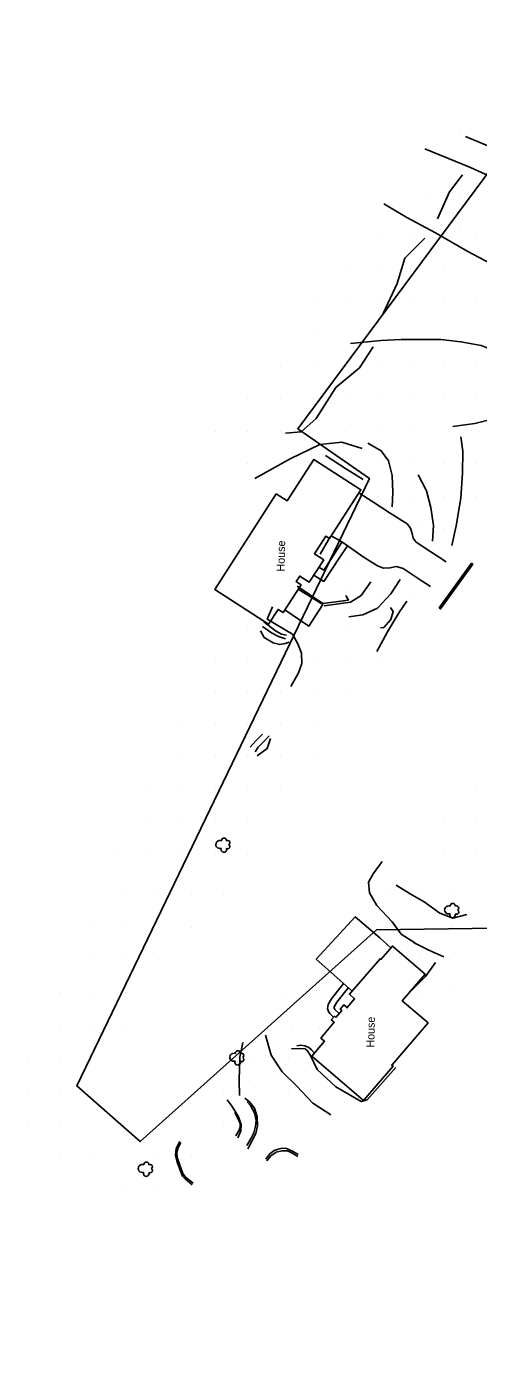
# Model space of a CAD drawing. Extents: x 19528164 to 19545171, y 7585743 to 7602745.
# Drawn here: x 19530134 to 19530412, y 7589849 to 7590664 of the extents above; entities that cross this region are included whole.
import ezdxf

# ---------------------------------------------------------------- set-up
doc = ezdxf.new("R2010")
doc.units = 0
for name, color, linetype in [('PhoBreakLine', 7, 'Continuous'), ('PhoBuilding', 7, 'Continuous'), ('PhoConcreteSlab', 7, 'Continuous'), ('PhoCulvert', 7, 'Continuous'), ('PhoEdgeEntrancePaved', 7, 'Continuous'), ('PhoEdgeSidewalk', 7, 'Continuous'), ('PhoISAEPoints', 7, 'Continuous'), ('PhoNotesDesign', 7, 'Continuous'), ('PhoRetainingWall', 7, 'Continuous'), ('PhoSurveyLimits', 7, 'Continuous'), ('PhoVegetation', 7, 'Continuous')]:
    doc.layers.add(name, color=color, linetype=linetype)

msp = doc.modelspace()

# ---------------------------------------------------------------- linework, layer by layer
at = {"layer": 'PhoBreakLine'}
msp.add_line((19530314.36, 7590339.33), (19530320.5, 7590350.04), dxfattribs=at)
for points in [[(19530403.61, 7590596.1), (19530418.38, 7590589.9), (19530432.36, 7590583.52), (19530438.39, 7590577.61), (19530460.96, 7590568.14), (19530473.26, 7590563.33)], [(19530378.62, 7590588.6), (19530406.66, 7590577.14), (19530432.03, 7590565.59), (19530461.15, 7590553.18), (19530486.35, 7590541.22), (19530503.6, 7590532.1)], [(19530386.5, 7590545.53), (19530393.89, 7590562.23), (19530401.77, 7590572.56)], [(19530479.66, 7590482.75), (19530468.31, 7590489.71), (19530454.31, 7590498.48), (19530439.34, 7590506.63), (19530422.54, 7590516.14), (19530405.06, 7590525.46), (19530385.22, 7590536.94), (19530367.64, 7590546.45), (19530353.47, 7590554.82)], [(19530353.07, 7590487.36), (19530361.78, 7590505.73), (19530366.36, 7590521.43), (19530378.64, 7590533.64)], [(19530502.39, 7590491.11), (19530496.31, 7590483.44), (19530489.96, 7590476.5), (19530483.54, 7590468.94), (19530483.54, 7590468.94), (19530476.74, 7590460.48), (19530471.42, 7590454.04), (19530465.97, 7590448.64), (19530460.11, 7590444.11), (19530453.81, 7590439.85), (19530453.66, 7590439.69), (19530447.39, 7590435.22), (19530438.51, 7590429.95), (19530430.65, 7590425.82), (19530420.97, 7590422.56), (19530409.38, 7590419.78), (19530395.92, 7590417.93)], [(19530471.42, 7590454.04), (19530466.34, 7590452.45), (19530457.67, 7590454), (19530445.09, 7590456.61), (19530432.58, 7590460.5), (19530423.57, 7590463.49), (19530413.26, 7590467.63), (19530400.84, 7590469.96), (19530388.45, 7590471.4), (19530374.92, 7590471.35), (19530364.22, 7590471.36), (19530351.67, 7590470.74), (19530333.08, 7590468.91)], [(19530293.09, 7590413.81), (19530302.65, 7590414.63), (19530311.85, 7590422.89), (19530323.97, 7590441.86), (19530338.59, 7590453.99), (19530347.02, 7590466.81)], [(19530274.18, 7590386.01), (19530295.87, 7590398.02), (19530314.16, 7590406.82), (19530327.61, 7590408.34), (19530340.09, 7590404.41)], [(19530358.56, 7590368.47), (19530359.03, 7590377.48), (19530358.71, 7590387.72), (19530356.37, 7590396.83), (19530351.82, 7590403.02), (19530343.65, 7590407.58)], [(19530395.3, 7590344.82), (19530397.89, 7590356.86), (19530400.88, 7590373.93), (19530401.92, 7590389.17), (19530402.11, 7590402.82), (19530400.88, 7590411.54)], [(19530317.73, 7590400.04), (19530330.62, 7590391.73), (19530340.85, 7590385.22)], [(19530383.33, 7590347.47), (19530384.09, 7590357.15), (19530382.43, 7590368.2), (19530379.68, 7590378.43), (19530379.12, 7590379.6), (19530374.58, 7590388.09)], [(19530331.88, 7590300.96), (19530340.62, 7590302.04), (19530349.52, 7590306.34), (19530357.83, 7590314.95), (19530363.61, 7590323.81)], [(19530300.21, 7590319.8), (19530315.99, 7590309.1), (19530331.71, 7590311.17), (19530330.12, 7590314.08)], [(19530316.92, 7590307.62), (19530327.06, 7590309.02), (19530332.96, 7590309.97), (19530339.57, 7590314.04), (19530345.55, 7590322.41)], [(19530285.16, 7590307), (19530281.82, 7590299.45), (19530297.3, 7590290.33), (19530300.55, 7590284.35), (19530302.95, 7590278.54), (19530303.15, 7590272.26), (19530301.14, 7590266.4), (19530296.35, 7590258.05)], [(19530349.17, 7590279.63), (19530355.8, 7590291.67), (19530363.09, 7590304.04), (19530367.7, 7590310.44)], [(19530357.58, 7590306.66), (19530359.3, 7590304.17), (19530357.7, 7590299.34), (19530353.47, 7590294.38), (19530351.4, 7590294.13)], [(19530277.78, 7590292.26), (19530280.04, 7590288.18), (19530285.51, 7590284.84), (19530289.49, 7590283.81), (19530292.87, 7590284.59), (19530295.37, 7590285.41)], [(19530278.89, 7590295.07), (19530284.43, 7590291.04), (19530288.67, 7590288.74), (19530293.16, 7590287.35)], [(19530271.42, 7590220.76), (19530274.67, 7590224.57), (19530278.99, 7590228.8)], [(19530274.4, 7590218.03), (19530276.29, 7590220.77), (19530280.29, 7590224.91), (19530283.05, 7590227.86)], [(19530275.68, 7590215.43), (19530281.77, 7590219.96), (19530283.92, 7590226.04)], [(19530372.47, 7590100.46), (19530364.22, 7590105.87), (19530358.63, 7590113.42), (19530349.29, 7590123.58), (19530344.63, 7590131.28), (19530344, 7590137.88), (19530346.99, 7590143.04), (19530352.55, 7590150.62)], [(19530361.11, 7590136.08), (19530369.6, 7590130.63), (19530378.35, 7590125.69), (19530387.87, 7590118.73), (19530395.8, 7590115.7), (19530404.42, 7590117.9)], [(19530372.22, 7590100.63), (19530381.19, 7590096.1), (19530390.3, 7590091.93)], [(19530369.6, 7590070.5), (19530379.18, 7590079.78), (19530385.27, 7590088.35)], [(19530264.87, 7590006.7), (19530264.66, 7590016.21), (19530265.08, 7590030.34), (19530266.83, 7590039.35)], [(19530280.77, 7590043.73), (19530284.2, 7590031.42), (19530291.01, 7590021.16), (19530299.97, 7590012.45), (19530309.81, 7590001.97), (19530320.88, 7589994.74)], [(19530296.69, 7590035.42), (19530301.87, 7590035.62), (19530305.13, 7590035.33), (19530306.64, 7590034.17), (19530308.38, 7590031.35), (19530312.61, 7590022.6), (19530324, 7590012.11), (19530339.57, 7590002.92), (19530343.23, 7590004.12), (19530360.78, 7590023.84)], [(19530263.83, 7589980.6), (19530265.52, 7589984.96), (19530265.73, 7589988.66), (19530264.21, 7589993.54), (19530260.33, 7590000.04), (19530257.11, 7590004.05)], [(19530269.89, 7589974.02), (19530274.79, 7589983.34), (19530275.78, 7589988), (19530275.68, 7589993.52), (19530273.91, 7589998.85), (19530271.01, 7590002.9), (19530268.14, 7590004.97)], [(19530228.03, 7589978.47), (19530225.81, 7589974.07), (19530225.36, 7589970), (19530226.5, 7589965.75), (19530228.41, 7589960.91), (19530229.84, 7589957.13), (19530231.42, 7589955.45), (19530235.62, 7589951.87)], [(19530281.64, 7589966.54), (19530284.04, 7589969.59), (19530287.29, 7589971.85), (19530290.89, 7589972.74), (19530294.21, 7589972.74), (19530296.6, 7589971.76), (19530300.63, 7589969.22)]]:
    msp.add_lwpolyline(points, dxfattribs=at)
at = {"layer": 'PhoBuilding'}
for points in [[(19530287.38, 7590376.46), (19530249.53, 7590317.78), (19530282.66, 7590296.41), (19530288.5, 7590305.46), (19530291.53, 7590303.5), (19530302.61, 7590320.68), (19530299.64, 7590322.59), (19530301.83, 7590325.99), (19530307.68, 7590322.22), (19530316.53, 7590335.94), (19530310.82, 7590339.62), (19530317.8, 7590350.43), (19530320.05, 7590348.98), (19530339.42, 7590379.01), (19530310.53, 7590397.65), (19530294.08, 7590372.14)], [(19530340.98, 7590003.56), (19530309.23, 7590030.88), (19530317.07, 7590040), (19530314.71, 7590042.04), (19530323.01, 7590051.69), (19530321.22, 7590053.23), (19530323.11, 7590055.42), (19530323.95, 7590054.69), (19530327.63, 7590058.97), (19530326.64, 7590059.81), (19530328.94, 7590062.48), (19530331.07, 7590060.65), (19530330.97, 7590060.54), (19530330.81, 7590060.68), (19530335.56, 7590066.19), (19530332.38, 7590068.93), (19530351.17, 7590090.76), (19530351.69, 7590090.31), (19530358.78, 7590098.55), (19530378.86, 7590081.27), (19530364.81, 7590064.94), (19530380.7, 7590051.27), (19530358.36, 7590025.31), (19530359.13, 7590024.65)]]:
    msp.add_lwpolyline(points, close=True, dxfattribs=at)
at = {"layer": 'PhoConcreteSlab'}
msp.add_lwpolyline([(19530292.6, 7590305.15), (19530307.44, 7590295.23), (19530316.06, 7590308.39), (19530300.86, 7590317.97)], dxfattribs=at)
at = {"layer": 'PhoCulvert'}
msp.add_line((19530387.52, 7590306.39), (19530407.28, 7590333.91), dxfattribs=at)
msp.add_lwpolyline([(19530387.52, 7590306.39), (19530388.33, 7590305.81), (19530408.1, 7590333.33), (19530407.28, 7590333.91)], dxfattribs=at)
at = {"layer": 'PhoEdgeEntrancePaved'}
for points in [[(19530391.88, 7590334.64), (19530377.61, 7590343.85), (19530373.09, 7590347.04), (19530371.6, 7590349.25), (19530370.98, 7590352.17), (19530369.91, 7590355.51), (19530367.73, 7590358.03), (19530357.35, 7590364.65), (19530346.75, 7590371.63), (19530338.16, 7590377.05)], [(19530321.21, 7590350.78), (19530327.64, 7590346.96), (19530341.44, 7590337.43), (19530349.55, 7590332.22), (19530353.28, 7590330.77), (19530357.22, 7590330.94), (19530361.29, 7590331.79), (19530365.28, 7590330.62), (19530376.47, 7590323.24), (19530382.25, 7590319.48)], [(19530334.1, 7590070.92), (19530311.95, 7590090.4), (19530323.95, 7590103.55), (19530335.78, 7590116.48), (19530351.06, 7590103.65), (19530357.79, 7590097.39)]]:
    msp.add_lwpolyline(points, dxfattribs=at)
at = {"layer": 'PhoEdgeSidewalk'}
for points in [[(19530331.08, 7590344.59), (19530326.53, 7590337.64), (19530316.68, 7590322.7), (19530310.45, 7590326.51)], [(19530327.77, 7590346.87), (19530320.87, 7590336.24), (19530316.57, 7590329.66), (19530313.6, 7590331.39)], [(19530328.78, 7590075.6), (19530321.34, 7590066.21), (19530319.24, 7590062.54), (19530318.96, 7590060.26), (19530319.58, 7590058.43), (19530320.3, 7590057.19), (19530322.65, 7590054.89)], [(19530331.75, 7590072.99), (19530324.62, 7590064), (19530323.07, 7590061.27), (19530322.99, 7590060.68), (19530323.2, 7590060.07), (19530323.45, 7590059.64), (19530326.03, 7590057.12)]]:
    msp.add_lwpolyline(points, dxfattribs=at)
at = {"layer": 'PhoISAEPoints'}
for p, q in [((19530400, 7590600), (19530400, 7590600)), ((19530380, 7590560), (19530380, 7590560)), ((19530400, 7590560), (19530400, 7590560)), ((19530350, 7590535), (19530350, 7590535)), ((19530370, 7590535), (19530370, 7590535)), ((19530400, 7590540), (19530400, 7590540)), ((19530410, 7590535), (19530410, 7590535)), ((19530330, 7590515), (19530330, 7590515)), ((19530350, 7590515), (19530350, 7590515)), ((19530370, 7590515), (19530370, 7590515)), ((19530390, 7590515), (19530390, 7590515)), ((19530310, 7590495), (19530310, 7590495)), ((19530330, 7590495), (19530330, 7590495)), ((19530350, 7590495), (19530350, 7590495)), ((19530370, 7590495), (19530370, 7590495)), ((19530390, 7590495), (19530390, 7590495)), ((19530410, 7590495), (19530410, 7590495)), ((19530310, 7590475), (19530310, 7590475)), ((19530290, 7590455), (19530290, 7590455)), ((19530310, 7590455), (19530310, 7590455)), ((19530330, 7590455), (19530330, 7590455)), ((19530350, 7590455), (19530350, 7590455)), ((19530370, 7590455), (19530370, 7590455)), ((19530390, 7590455), (19530390, 7590455)), ((19530410, 7590455), (19530410, 7590455)), ((19530270, 7590435), (19530270, 7590435)), ((19530290, 7590435), (19530290, 7590435)), ((19530310, 7590435), (19530310, 7590435)), ((19530330, 7590435), (19530330, 7590435)), ((19530350, 7590435), (19530350, 7590435)), ((19530370, 7590435), (19530370, 7590435)), ((19530390, 7590435), (19530390, 7590435)), ((19530410, 7590435), (19530410, 7590435)), ((19530250, 7590415), (19530250, 7590415)), ((19530270, 7590415), (19530270, 7590415)), ((19530290, 7590415), (19530290, 7590415)), ((19530310, 7590415), (19530310, 7590415)), ((19530330, 7590415), (19530330, 7590415)), ((19530350, 7590415), (19530350, 7590415)), ((19530370, 7590415), (19530370, 7590415)), ((19530331.38, 7590397.99), (19530331.38, 7590397.99)), ((19530270, 7590395), (19530270, 7590395)), ((19530350, 7590395), (19530350, 7590395)), ((19530370, 7590395), (19530370, 7590395)), ((19530390, 7590395), (19530390, 7590395)), ((19530410, 7590395), (19530410, 7590395)), ((19530293.44, 7590383.22), (19530293.44, 7590383.22)), ((19530350, 7590375), (19530350, 7590375)), ((19530370, 7590375), (19530370, 7590375)), ((19530390, 7590375), (19530390, 7590375)), ((19530410, 7590375), (19530410, 7590375)), ((19530329.64, 7590364.3), (19530329.64, 7590364.3)), ((19530376.41, 7590358.31), (19530376.41, 7590358.31)), ((19530390, 7590355), (19530390, 7590355)), ((19530330, 7590335), (19530330, 7590335)), ((19530350, 7590335), (19530350, 7590335)), ((19530370, 7590335), (19530370, 7590335)), ((19530312.57, 7590318.77), (19530312.57, 7590318.77)), ((19530333.23, 7590317.59), (19530333.23, 7590317.59)), ((19530350, 7590315), (19530350, 7590315)), ((19530370, 7590315), (19530370, 7590315)), ((19530270, 7590295), (19530270, 7590295)), ((19530294.17, 7590297.6), (19530294.17, 7590297.6)), ((19530310, 7590295), (19530310, 7590295)), ((19530330, 7590295), (19530330, 7590295)), ((19530350, 7590295), (19530350, 7590295)), ((19530250, 7590275), (19530250, 7590275)), ((19530270, 7590275), (19530270, 7590275)), ((19530290, 7590275), (19530290, 7590275)), ((19530310, 7590275), (19530310, 7590275)), ((19530330, 7590275), (19530330, 7590275)), ((19530350, 7590275), (19530350, 7590275)), ((19530250, 7590255), (19530250, 7590255)), ((19530270, 7590255), (19530270, 7590255)), ((19530290, 7590255), (19530290, 7590255)), ((19530310, 7590255), (19530310, 7590255)), ((19530330, 7590255), (19530330, 7590255)), ((19530230, 7590235), (19530230, 7590235)), ((19530250, 7590235), (19530250, 7590235)), ((19530270, 7590235), (19530270, 7590235)), ((19530290, 7590235), (19530290, 7590235)), ((19530310, 7590235), (19530310, 7590235)), ((19530230, 7590215), (19530230, 7590215)), ((19530250, 7590215), (19530250, 7590215)), ((19530270, 7590215), (19530270, 7590215)), ((19530290, 7590215), (19530290, 7590215)), ((19530310, 7590215), (19530310, 7590215)), ((19530210, 7590195), (19530210, 7590195)), ((19530230, 7590195), (19530230, 7590195)), ((19530250, 7590195), (19530250, 7590195)), ((19530270, 7590195), (19530270, 7590195)), ((19530290, 7590195), (19530290, 7590195)), ((19530410, 7590195), (19530410, 7590195)), ((19530210, 7590175), (19530210, 7590175)), ((19530230, 7590175), (19530230, 7590175)), ((19530250, 7590175), (19530250, 7590175)), ((19530270, 7590175), (19530270, 7590175)), ((19530390, 7590175), (19530390, 7590175)), ((19530410, 7590175), (19530410, 7590175)), ((19530190, 7590155), (19530190, 7590155)), ((19530210, 7590155), (19530210, 7590155)), ((19530230, 7590155), (19530230, 7590155)), ((19530250, 7590155), (19530250, 7590155)), ((19530270, 7590155), (19530270, 7590155)), ((19530390, 7590155), (19530390, 7590155)), ((19530410, 7590155), (19530410, 7590155)), ((19530195, 7590130), (19530195, 7590130)), ((19530215, 7590130), (19530215, 7590130)), ((19530235, 7590130), (19530235, 7590130)), ((19530255, 7590130), (19530255, 7590130)), ((19530356.78, 7590130.58), (19530356.78, 7590130.58)), ((19530375.04, 7590131.79), (19530375.04, 7590131.79)), ((19530394.11, 7590132.07), (19530394.11, 7590132.07)), ((19530175, 7590110), (19530175, 7590110)), ((19530195, 7590110), (19530195, 7590110)), ((19530215, 7590110), (19530215, 7590110)), ((19530235, 7590110), (19530235, 7590110)), ((19530355, 7590110), (19530355, 7590110)), ((19530375, 7590110), (19530375, 7590110)), ((19530395, 7590110), (19530395, 7590110)), ((19530175, 7590090), (19530175, 7590090)), ((19530195, 7590090), (19530195, 7590090)), ((19530215, 7590090), (19530215, 7590090)), ((19530335, 7590090), (19530335, 7590090)), ((19530375.89, 7590092.79), (19530375.89, 7590092.79)), ((19530394.12, 7590090.45), (19530394.12, 7590090.45)), ((19530312.4, 7590071.36), (19530312.4, 7590071.36)), ((19530394.57, 7590072.45), (19530394.57, 7590072.45)), ((19530155, 7590070), (19530155, 7590070)), ((19530175, 7590070), (19530175, 7590070)), ((19530195, 7590070), (19530195, 7590070)), ((19530292.82, 7590068.01), (19530292.82, 7590068.01)), ((19530377.17, 7590067.31), (19530377.17, 7590067.31)), ((19530155, 7590050), (19530155, 7590050)), ((19530175, 7590050), (19530175, 7590050)), ((19530195, 7590050), (19530195, 7590050)), ((19530296.56, 7590048.92), (19530296.56, 7590048.92)), ((19530313.84, 7590048.75), (19530313.84, 7590048.75)), ((19530135, 7590030), (19530135, 7590030)), ((19530155, 7590030), (19530155, 7590030)), ((19530175, 7590030), (19530175, 7590030)), ((19530295, 7590030), (19530295, 7590030)), ((19530273.57, 7590029.62), (19530273.57, 7590029.62)), ((19530305.6, 7590021.43), (19530305.6, 7590021.43)), ((19530135, 7590010), (19530135, 7590010)), ((19530155, 7590010), (19530155, 7590010)), ((19530255, 7590010), (19530255, 7590010)), ((19530274.16, 7590011.9), (19530274.16, 7590011.9)), ((19530295, 7590010), (19530295, 7590010)), ((19530135, 7589990), (19530135, 7589990)), ((19530155, 7589990), (19530155, 7589990)), ((19530255, 7589990), (19530255, 7589990)), ((19530275, 7589990), (19530275, 7589990)), ((19530155, 7589970), (19530155, 7589970)), ((19530175, 7589970), (19530175, 7589970)), ((19530215, 7589970), (19530215, 7589970)), ((19530235, 7589970), (19530235, 7589970)), ((19530195, 7589950), (19530195, 7589950)), ((19530195, 7589950), (19530195, 7589950)), ((19530215, 7589950), (19530215, 7589950))]:
    msp.add_line(p, q, dxfattribs=at)
at = {"layer": 'PhoRetainingWall'}
for points in [[(19530331.71, 7590311.17), (19530315.99, 7590309.1), (19530300.21, 7590319.8)], [(19530293.58, 7590289.67), (19530290.59, 7590290.36), (19530286.84, 7590292.35), (19530279.78, 7590297.85)], [(19530299.97, 7590037.25), (19530302.21, 7590037.54), (19530304.89, 7590037.24), (19530307.33, 7590036.19), (19530309.08, 7590034.76), (19530310.71, 7590032.97)], [(19530269.53, 7590002.81), (19530271.6, 7590000.65), (19530274, 7589996.02), (19530275.02, 7589991.4), (19530274.71, 7589987.77), (19530273.57, 7589983.79), (19530272.01, 7589980.39), (19530269.25, 7589975.91)], [(19530261.95, 7589996.26), (19530263.86, 7589992.76), (19530265.13, 7589989.47), (19530265.19, 7589987.22), (19530264.6, 7589985.3), (19530262.62, 7589981.93)], [(19530228.64, 7589977.91), (19530227.02, 7589974.77), (19530226.32, 7589971.66), (19530226.42, 7589968.55), (19530228.19, 7589963.98), (19530230.02, 7589958.76), (19530231.58, 7589956.43), (19530236.29, 7589952.92)], [(19530280.87, 7589967.62), (19530283.49, 7589970.77), (19530286.17, 7589972.94), (19530288.64, 7589973.7), (19530291.02, 7589974.26), (19530293.72, 7589974.03), (19530297.34, 7589972.55), (19530300.85, 7589970.42)]]:
    msp.add_lwpolyline(points, dxfattribs=at)
at = {"layer": 'PhoSurveyLimits'}
msp.add_lwpolyline([(19530813.08, 7588141.83), (19530826.36, 7590306.58), (19530836.02, 7590358.63), (19530806.78, 7590373.28), (19530757.47, 7590370.26), (19530695.18, 7590346.98), (19530641.2, 7590285.01), (19530612.99, 7590219.54), (19530561.32, 7590123.06), (19530451.92, 7590109.87), (19530349.02, 7590108.43), (19530203.76, 7589978.43), (19530164.76, 7590012.57), (19530344.64, 7590385.93), (19530300.57, 7590416.51), (19530480.77, 7590658.88), (19530687.59, 7591041.97), (19530295.19, 7591473.06), (19529551.78, 7591996.95)], dxfattribs=at)
at = {"layer": 'PhoVegetation'}
for centre, radius, start, end in [((19530252.69, 7590161.01), 2.46, 67.06585, 290.6557), ((19530255.25, 7590163.36), 1.6, 354.85897, 182.86258), ((19530257.59, 7590159.7), 1.34, 231.61092, 64.18311), ((19530257.6, 7590162.11), 1.34, 295.38494, 124.26412), ((19530255.15, 7590157.95), 1.76, 154.34317, 23.37831), ((19530393.28, 7590120.78), 2.46, 67.06585, 290.6557), ((19530395.84, 7590123.12), 1.6, 354.85897, 182.86258), ((19530398.18, 7590119.46), 1.34, 231.61092, 64.18311), ((19530398.19, 7590121.88), 1.34, 295.38494, 124.26412), ((19530395.73, 7590117.71), 1.76, 154.34317, 23.37831), ((19530261.27, 7590030.22), 2.46, 67.06585, 290.6557), ((19530263.83, 7590032.57), 1.6, 354.85897, 182.86258), ((19530266.17, 7590028.91), 1.34, 231.61092, 64.18311), ((19530266.18, 7590031.32), 1.34, 295.38494, 124.26412), ((19530263.73, 7590027.16), 1.76, 154.34317, 23.37831), ((19530207.56, 7589964.19), 1.6, 354.85897, 182.86258), ((19530205, 7589961.85), 2.46, 67.06585, 290.6557), ((19530207.45, 7589958.78), 1.76, 154.34317, 23.37831), ((19530209.9, 7589960.53), 1.34, 231.61092, 64.18311), ((19530209.91, 7589962.95), 1.34, 295.38494, 124.26412)]:
    msp.add_arc(centre, radius, start, end, dxfattribs=at)

# ---------------------------------------------------------------- texts
at = {"layer": 'PhoNotesDesign'}
for p in [(19530292.48, 7590328.74), (19530347.63, 7590036.09)]:
    msp.add_text('House', height=4.92, rotation=88.86078, dxfattribs=at).set_placement(p)

doc.saveas('drawing.dxf')
